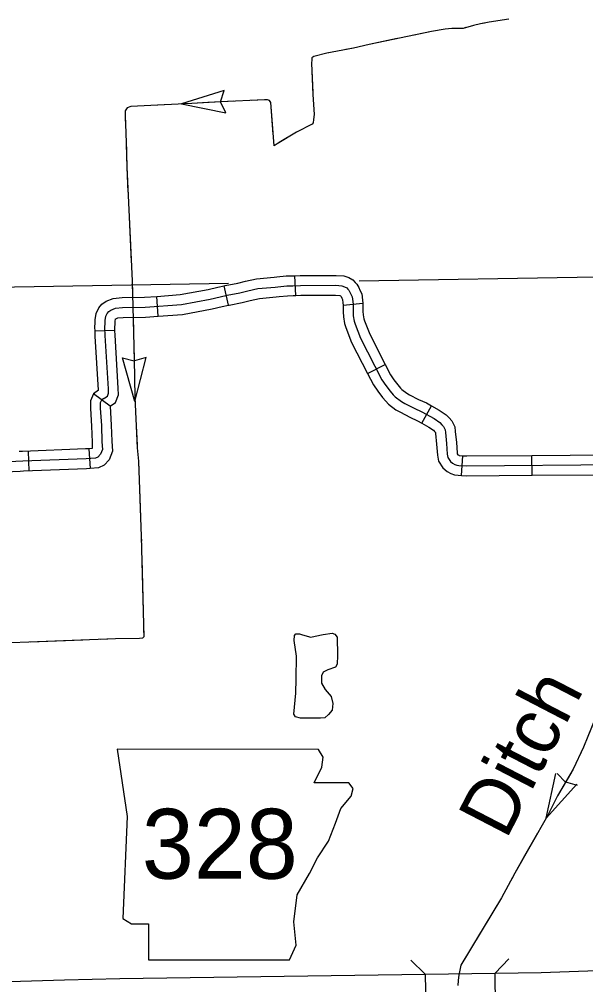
# Model space of a CAD drawing. Extents: x 1164457 to 1439835, y 1590918 to 1773502.
# Drawn here: x 1271793 to 1276072, y 1650267 to 1657559 of the extents above; entities that cross this region are included whole.
import ezdxf

# ---------------------------------------------------------------- set-up
doc = ezdxf.new("R2010")
doc.units = 0
for name, color, linetype in [('Level 10', 7, 'Continuous'), ('Level 21', 7, 'Continuous'), ('Level 32', 7, 'Continuous'), ('Level 35', 7, 'Continuous'), ('Level 37', 7, 'Continuous'), ('Level 43', 7, 'Continuous'), ('Level 5', 7, 'Continuous')]:
    doc.layers.add(name, color=color, linetype=linetype)

msp = doc.modelspace()

# ---------------------------------------------------------------- linework, layer by layer
at = {"layer": 'Level 10'}
for points in [[(1275387.7, 1650354.7), (1275736.8, 1650359.7), (1276513.8, 1650385.7), (1277876.7, 1650436.9), (1281930.7, 1650594.7), (1283252.9, 1650656.4), (1283325.4, 1650660.3), (1283338.7, 1650410.6)], [(1283338.7, 1650410.6), (1283265.3, 1650406.7), (1281941.4, 1650344.9), (1277886.3, 1650187.1), (1276522.7, 1650135.9), (1275742.8, 1650109.7), (1275391.3, 1650104.7), (1275387.7, 1650354.7)], [(1265354.2, 1650177.4), (1265700.9, 1650190.4), (1265810, 1650187.7), (1265879.2, 1650182.5), (1265921.6, 1650180.7), (1265991.5, 1650176.2), (1266041.1, 1650172.5), (1266123.4, 1650170), (1266239.4, 1650160.8), (1266306.1, 1650157), (1266383, 1650156.5), (1266450.8, 1650157.4), (1266517.3, 1650158.2), (1270335.3, 1650243.9), (1271220.7, 1650275.2), (1272134.5, 1650304.4), (1272553.4, 1650313.8), (1274859.7, 1650347.1), (1274863.3, 1650097.1)], [(1274859.7, 1650347.1), (1275387.7, 1650354.7)]]:
    msp.add_lwpolyline(points, dxfattribs=at)
at = {"layer": 'Level 21'}
msp.add_lwpolyline([(1272531.3, 1652045), (1272607.4, 1651537.4), (1272573.6, 1650767.7), (1272641.3, 1650725.4), (1272768.2, 1650725.4), (1272768.2, 1650454.7), (1273834, 1650454.7), (1273884.7, 1650564.7), (1273867.8, 1650742.3), (1273893.2, 1650945.3), (1273986.2, 1651106), (1274045.5, 1651224.5), (1274130, 1651351.3), (1274180.8, 1651486.7), (1274223.1, 1651596.6), (1274299.2, 1651689.7), (1274316.1, 1651748.9), (1274282.3, 1651791.2), (1274020.1, 1651791.2), (1274079.3, 1651909.6), (1274087.7, 1651985.8), (1274052.7, 1652044.2)], close=True, dxfattribs=at)
at = {"layer": 'Level 32'}
for p, q in [((1273881.8, 1655472.6), (1273874.4, 1655622.4)), ((1273373.1, 1655399.7), (1273340.5, 1655546.1)), ((1272841.5, 1655316.7), (1272830.8, 1655466.3)), ((1274239.4, 1655399.6), (1274388.7, 1655414.1)), ((1272515.3, 1655208.4), (1272365.4, 1655202.2)), ((1274424.3, 1654883.2), (1274557.7, 1654951.8)), ((1272478.9, 1654635.7), (1272353.1, 1654729.9)), ((1274833.5, 1654508.6), (1274906.8, 1654639.5)), ((1271858.8, 1654296.9), (1271865.5, 1654147)), ((1272318.1, 1654315), (1272328.8, 1654165.4)), ((1275133.9, 1654113.1), (1275142.8, 1654262.8)), ((1275666.9, 1654114.9), (1275665.7, 1654264.9))]:
    msp.add_line(p, q, dxfattribs=at)
for points in [[(1273340.5, 1655546.1), (1273347.5, 1655547.7), (1273443.1, 1655565.2), (1273502.3, 1655580.7), (1273584.6, 1655599.3), (1273717.8, 1655610.9), (1273738.3, 1655613.6), (1273809.7, 1655620), (1273855.7, 1655621.5), (1273874.4, 1655622.4)], [(1273874.4, 1655622.4), (1273915.6, 1655624.4), (1274188, 1655625), (1274244.6, 1655621.1), (1274282.1, 1655607.7), (1274313.2, 1655589.8), (1274330.1, 1655571.9), (1274342.8, 1655557.6), (1274357.8, 1655533.5), (1274366.9, 1655512.2), (1274379.5, 1655484.2), (1274386.5, 1655436.3), (1274388.7, 1655414.1)], [(1272430.9, 1654693.6), (1272439.8, 1654700), (1272457.8, 1654712.9), (1272466.8, 1654736), (1272465.5, 1654768), (1272441.8, 1655170.4), (1272439.2, 1655232), (1272441.8, 1655262.8), (1272441.8, 1655284.7), (1272446.3, 1655315.5), (1272456.5, 1655337.8), (1272468.1, 1655351.4), (1272484.7, 1655362.9), (1272519.4, 1655377.1), (1272573.3, 1655382.2), (1272742.6, 1655384.8), (1273017.1, 1655404.5), (1273234.5, 1655445.2), (1273310.1, 1655462.5), (1273362.4, 1655474.2), (1273459.4, 1655491.9), (1273520.1, 1655507.8), (1273596.1, 1655525), (1273726.1, 1655536.3), (1273746.6, 1655539.1), (1273814.2, 1655545.1), (1273858.7, 1655546.5), (1273917.5, 1655549.4), (1274185.5, 1655550), (1274229.1, 1655546.9), (1274250.5, 1655539.3), (1274266.3, 1655530.3), (1274274.9, 1655521.2), (1274282.5, 1655512.6), (1274291.1, 1655498.8), (1274298.2, 1655482.1), (1274306.8, 1655463), (1274312.1, 1655427.2), (1274314.3, 1655404.4), (1274314.2, 1655375.5), (1274314.3, 1655350.4), (1274315.9, 1655319.6), (1274321.9, 1655279.8), (1274330, 1655255.4), (1274371.8, 1655149.2), (1274532.9, 1654836.1), (1274561.8, 1654793), (1274594.7, 1654749.5), (1274617.9, 1654723.4), (1274633.1, 1654706.4), (1274679.4, 1654671.6), (1274706.9, 1654656.9), (1274775.6, 1654620.6), (1274835.2, 1654593.7), (1274926.2, 1654542.7), (1274969.7, 1654513.4), (1274985.7, 1654496.7), (1274997.6, 1654483.1), (1275010.1, 1654458.6), (1275011.9, 1654438.6), (1275020.5, 1654355.4), (1275026.3, 1654275), (1275030.9, 1654249.9), (1275049.6, 1654219.8), (1275066.3, 1654205.3), (1275083.7, 1654197), (1275098.4, 1654190.8), (1275113.4, 1654189.4), (1275171.2, 1654186), (1276323.7, 1654195.1)], [(1272830.8, 1655466.3), (1273007.4, 1655479), (1273219.2, 1655518.6), (1273293.5, 1655535.7), (1273340.5, 1655546.1)], [(1272365.4, 1655202.2), (1272364.1, 1655233.6), (1272366.8, 1655266), (1272366.8, 1655290.1), (1272373.6, 1655336.9), (1272392.7, 1655378.5), (1272417.3, 1655407.5), (1272448.8, 1655429.3), (1272501.3, 1655450.7), (1272569.1, 1655457.1), (1272739.3, 1655459.7), (1272830.8, 1655466.3)], [(1273373.1, 1655399.7), (1273377.3, 1655400.7), (1273475.7, 1655418.6), (1273537.9, 1655434.9), (1273607.7, 1655450.7), (1273734.4, 1655461.7), (1273755, 1655464.5), (1273818.8, 1655470.2), (1273861.8, 1655471.6), (1273881.8, 1655472.6)], [(1273881.8, 1655472.6), (1273919.4, 1655474.4), (1274183, 1655475), (1274213.6, 1655472.8), (1274219, 1655470.9), (1274219.4, 1655470.7), (1274219.6, 1655470.5), (1274222.2, 1655467.6), (1274224.4, 1655464), (1274229.6, 1655451.9), (1274234.1, 1655441.8), (1274237.6, 1655418.2), (1274239.4, 1655399.6)], [(1272841.5, 1655316.7), (1273026.7, 1655330), (1273249.8, 1655371.7), (1273326.6, 1655389.4), (1273373.1, 1655399.7)], [(1274239.3, 1655400.9), (1274239.2, 1655375.5), (1274239.3, 1655348.4), (1274241.2, 1655312.1), (1274248.7, 1655262.2), (1274259.5, 1655229.8), (1274303.4, 1655118.3), (1274424.3, 1654883.2)], [(1274388.7, 1655414.1), (1274389.3, 1655408), (1274389.2, 1655375.6), (1274389.3, 1655352.5), (1274390.6, 1655327.2), (1274395.1, 1655297.3), (1274400.6, 1655281), (1274440.2, 1655180.2), (1274557.7, 1654951.8)], [(1272515.3, 1655208.4), (1272514.3, 1655230.5), (1272516.8, 1655259.7), (1272516.8, 1655279.2), (1272518.9, 1655294), (1272519.9, 1655296), (1272520.7, 1655296.6), (1272537.5, 1655303.4), (1272577.4, 1655307.2), (1272745.9, 1655309.8), (1272841.5, 1655316.7)], [(1272391, 1654757.3), (1272366.9, 1655166.7), (1272365.4, 1655202.2)], [(1272478.9, 1654635.7), (1272519.6, 1654664.8), (1272542.3, 1654723.3), (1272540.4, 1654771.7), (1272516.7, 1655174.2), (1272515.3, 1655208.4)], [(1274557.7, 1654951.8), (1274597.6, 1654874.2), (1274622.9, 1654836.6), (1274652.7, 1654797.2), (1274674, 1654773.3), (1274684.1, 1654761.9), (1274719.8, 1654735), (1274742.1, 1654723.1), (1274808.6, 1654688), (1274869, 1654660.7), (1274906.8, 1654639.5)], [(1274424.3, 1654883.2), (1274468.2, 1654797.9), (1274500.7, 1654749.5), (1274536.7, 1654701.8), (1274561.9, 1654673.5), (1274582, 1654651), (1274638.9, 1654608.2), (1274671.8, 1654590.6), (1274742.6, 1654553.2), (1274801.3, 1654526.7), (1274833.5, 1654508.6)], [(1272391, 1654757.3), (1272353.1, 1654729.9), (1272329.6, 1654676.5), (1272329.6, 1654619.8), (1272338, 1654486.1), (1272342.5, 1654365.1), (1272344.3, 1654321.7), (1272342.4, 1654316.7), (1272318.1, 1654315)], [(1272430.9, 1654693.6), (1272413.5, 1654681.1), (1272404.6, 1654660.7), (1272404.6, 1654622.2), (1272412.9, 1654489.9), (1272417.4, 1654368.1), (1272420, 1654309.1), (1272405.9, 1654273.1), (1272386.6, 1654252.6), (1272369.3, 1654243.5), (1272297.4, 1654238.3), (1271820.2, 1654220.4), (1271124.9, 1654189.6)], [(1272478.9, 1654635.7), (1272487.8, 1654493.6), (1272492.3, 1654371.1), (1272495.6, 1654296.4), (1272470.4, 1654232.3), (1272432.7, 1654192.1), (1272390.3, 1654169.8), (1272328.8, 1654165.4)], [(1274906.8, 1654639.5), (1274965.5, 1654606.6), (1275018.2, 1654571.2), (1275041.1, 1654547.4), (1275060.3, 1654525.3), (1275083.4, 1654479.8), (1275086.6, 1654446), (1275095.3, 1654361.9), (1275100.8, 1654284.5), (1275102.1, 1654277.4), (1275107.3, 1654269), (1275107.7, 1654268.7), (1275114.6, 1654265.4), (1275116.9, 1654264.4), (1275119.1, 1654264.2), (1275142.8, 1654262.8)], [(1274833.5, 1654508.6), (1274886.9, 1654478.7), (1274921.2, 1654455.6), (1274930.4, 1654446.1), (1274934.9, 1654440.9), (1274936.7, 1654437.3), (1274937.3, 1654431.3), (1274945.8, 1654348.8), (1274951.8, 1654265.4), (1274959.8, 1654222.4), (1274991.9, 1654170.5), (1275024.9, 1654142), (1275052.8, 1654128.7), (1275079.8, 1654117.2), (1275107.8, 1654114.6), (1275133.9, 1654113.1)], [(1272318.1, 1654315), (1272293.4, 1654313.2), (1271817.2, 1654295.3), (1271792.5, 1654294.2)], [(1275142.8, 1654262.8), (1275173.1, 1654261), (1275665.7, 1654264.9)], [(1275665.7, 1654264.9), (1276245.3, 1654269.5)], [(1271799.2, 1654144.4), (1271271.7, 1654121)], [(1272328.8, 1654165.4), (1272301.5, 1654163.4), (1271823.3, 1654145.4), (1271799.2, 1654144.4)], [(1275666.9, 1654114.9), (1276194.8, 1654119.1)], [(1275133.9, 1654113.1), (1275169.3, 1654111), (1275666.9, 1654114.9)]]:
    msp.add_lwpolyline(points, dxfattribs=at)
at = {"layer": 'Level 35'}
for points in [[(1273885.7, 1652577.5), (1273887.3, 1652748.8), (1273869.4, 1652867.8), (1273872.6, 1652903.7), (1273882.4, 1652916.7), (1273908.5, 1652916.7), (1273933, 1652910.2), (1273996.5, 1652892.3), (1274029.1, 1652900.4), (1274087.8, 1652911.8), (1274156.3, 1652921.6), (1274175.9, 1652915.1), (1274193.8, 1652892.3), (1274197.1, 1652753.6), (1274193.8, 1652686.8), (1274180.8, 1652665.6), (1274123.7, 1652644.4), (1274087.8, 1652628.1), (1274076.4, 1652598.7), (1274074.8, 1652572.6), (1274074.8, 1652544.9)], [(1274074.8, 1652544.9), (1274102.5, 1652497.6), (1274149.8, 1652443.8), (1274161.2, 1652391.6), (1274156.3, 1652341), (1274128.6, 1652306.8), (1274100.9, 1652282.3), (1274068.3, 1652280.7), (1274040.6, 1652280.7), (1273963.9, 1652280.7), (1273918.3, 1652280.7), (1273879.2, 1652288.8), (1273867.7, 1652310), (1273880.8, 1652469.9), (1273885.7, 1652577.5)]]:
    msp.add_lwpolyline(points, dxfattribs=at)
at = {"layer": 'Level 37'}
for points in [[(1274752.2, 1650451.6), (1274859.7, 1650347.1)], [(1275387.7, 1650354.7), (1275492.2, 1650462.2)]]:
    msp.add_lwpolyline(points, dxfattribs=at)
at = {"layer": 'Level 43'}
for p, q in [((1272664.7, 1654670.9), (1272572.2, 1655001.4)), ((1272572.2, 1655001.4), (1272660.7, 1654978.7)), ((1272749.9, 1655003.3), (1272661.9, 1654978.7)), ((1272664.7, 1654670.9), (1272749.9, 1655003.3)), ((1275774.8, 1651525.5), (1275846, 1651861.2)), ((1275856, 1651861.7), (1275920.2, 1651796.7)), ((1276009.3, 1651772), (1275921.2, 1651796.2)), ((1275774.8, 1651525.5), (1276004.4, 1651780.6))]:
    msp.add_line(p, q, dxfattribs=at)
for points in [[(1275490.7, 1657559), (1275341.7, 1657536.4), (1275278.5, 1657525.1), (1275224.3, 1657511.6), (1275145.8, 1657490.1), (1275061.2, 1657490.1), (1275010.4, 1657485.6), (1274906.5, 1657467.5), (1274435.2, 1657369.3), (1274317.3, 1657339.9), (1274115.8, 1657303.8), (1274018.7, 1657277.8), (1274004, 1657268.8), (1274001.7, 1657254.1), (1273999.8, 1657227.1), (1274010, 1656991.1), (1274020.6, 1656841.1), (1274015.2, 1656802.7), (1274012.2, 1656777.6), (1274004.3, 1656767.5), (1273886.9, 1656707.6), (1273740.6, 1656618.8), (1273718.7, 1656603.7), (1273693.9, 1656930.1), (1273683.7, 1656945.9), (1273667.9, 1656951.5), (1273644.8, 1656951.5), (1273314.2, 1656934.4), (1273096, 1656923.3)], [(1275490.7, 1657559), (1275341.7, 1657536.4), (1275295.1, 1657528.1)], [(1275167.1, 1657495.9), (1275145.8, 1657490.1), (1275061.2, 1657490.1), (1275010.4, 1657485.6), (1274906.5, 1657467.5), (1274776.5, 1657440.4)], [(1274647.3, 1657413.5), (1274435.2, 1657369.3), (1274317.3, 1657339.9), (1274260.3, 1657329.7)], [(1274130.4, 1657306.4), (1274115.8, 1657303.8), (1274018.7, 1657277.8), (1274004, 1657268.8), (1274001.7, 1657254.1), (1273999.8, 1657227.1), (1274009.3, 1657005.8)], [(1273312.5, 1656934.4), (1273340.2, 1657021.4), (1273019.2, 1656919.4)], [(1273096, 1656923.3), (1272736.4, 1656905), (1272634.4, 1656899.9), (1272607.3, 1656890.6), (1272591.5, 1656867.7), (1272593, 1656814.6), (1272598.7, 1656706.9), (1272604.4, 1656441.4), (1272645.1, 1655584.3), (1272661.2, 1654992.7), (1272664.4, 1654703.7), (1272683.6, 1654320.9), (1272692.6, 1654222.1), (1272714.4, 1653652.3), (1272733, 1652893.3), (1272722.7, 1652883.1), (1272699.6, 1652880.5), (1272520, 1652879.2), (1271074.6, 1652824.5)], [(1272887.3, 1656912.7), (1272736.4, 1656905), (1272634.4, 1656899.9), (1272607.3, 1656890.6), (1272591.5, 1656867.7), (1272593, 1656814.6), (1272594.7, 1656781.5)], [(1273019.2, 1656919.4), (1273352.6, 1656852.3), (1273312.5, 1656934.4)], [(1273216.9, 1656929.5), (1273096, 1656923.3), (1273019.2, 1656919.4)], [(1273414.7, 1656939.6), (1273314.2, 1656934.4), (1273216.9, 1656929.5)], [(1273712, 1656691.9), (1273693.9, 1656930.1), (1273683.7, 1656945.9), (1273667.9, 1656951.5), (1273644.8, 1656951.5), (1273546.5, 1656946.5)], [(1274018.2, 1656874.1), (1274020.6, 1656841.1), (1274015.2, 1656802.7), (1274012.2, 1656777.6), (1274004.3, 1656767.5), (1273886.9, 1656707.6), (1273755.1, 1656627.6)], [(1272599.9, 1656649.6), (1272604.4, 1656441.4), (1272613.3, 1656253.9)], [(1272619.6, 1656122), (1272638.4, 1655726.5)], [(1272644.6, 1655594.6), (1272645.1, 1655584.3), (1272648.5, 1655458.3)], [(1272652.6, 1655308.4), (1272655.6, 1655198.8)], [(1272659.1, 1655066.8), (1272661.2, 1654992.7), (1272664.4, 1654703.7), (1272666, 1654670.9)], [(1272672.6, 1654539.1), (1272682.6, 1654341.3)], [(1272682.6, 1654341.3), (1272683.6, 1654320.9), (1272692.6, 1654222.1), (1272695.6, 1654143.8)], [(1272700.6, 1654011.9), (1272714.4, 1653652.3), (1272715.3, 1653616.2)], [(1272718.5, 1653484.2), (1272728.2, 1653088.3)], [(1277764.5, 1653384.5), (1276712.4, 1653153), (1276517, 1653097.2), (1276493.6, 1653073.3), (1276472.2, 1653043.4), (1276453, 1652993), (1276353.1, 1652791.7), (1276089.1, 1652140.8), (1276054.5, 1652061.4), (1275978.6, 1651895.4), (1275860, 1651692.9), (1275783, 1651541.5), (1275535.6, 1651109.6), (1275436.9, 1650922.9), (1275130, 1650414), (1275117.8, 1650362.6), (1275114, 1650341), (1275108.8, 1650298.3), (1275107.2, 1650260.8)], [(1272731.4, 1652956.4), (1272733, 1652893.3), (1272722.7, 1652883.1), (1272699.6, 1652880.5), (1272520, 1652879.2), (1272404.5, 1652874.9)], [(1272272.6, 1652869.9), (1271876.9, 1652854.9)], [(1276176.5, 1652356.1), (1276089.1, 1652140.8), (1276054.5, 1652061.4), (1276022.5, 1651991.3)], [(1275965.2, 1651872.5), (1275860, 1651692.9), (1275783, 1651541.5), (1275774, 1651525.9)], [(1275708.4, 1651411.4), (1275610, 1651239.6)], [(1275610, 1651239.6), (1275535.6, 1651109.6), (1275513.1, 1651067)], [(1275451.4, 1650950.2), (1275436.9, 1650922.9), (1275248.4, 1650610.3)], [(1275180.2, 1650497.2), (1275130, 1650414), (1275115, 1650350.7)]]:
    msp.add_lwpolyline(points, dxfattribs=at)
at = {"layer": 'Level 5'}
for points in [[(1276155.3, 1655612.2), (1274361.8, 1655581.2)], [(1273374.1, 1655564.1), (1271167.3, 1655525.9)]]:
    msp.add_lwpolyline(points, dxfattribs=at)

# ---------------------------------------------------------------- texts
at = {"layer": 'Level 21'}
msp.add_text('328', height=528, dxfattribs=at).set_placement((1272718.5, 1651067.2))
at = {"layer": 'Level 43'}
msp.add_text('Ditch', height=422, rotation=62.60759, dxfattribs=at).set_placement((1275469.8, 1651354.3))

doc.saveas('drawing.dxf')
